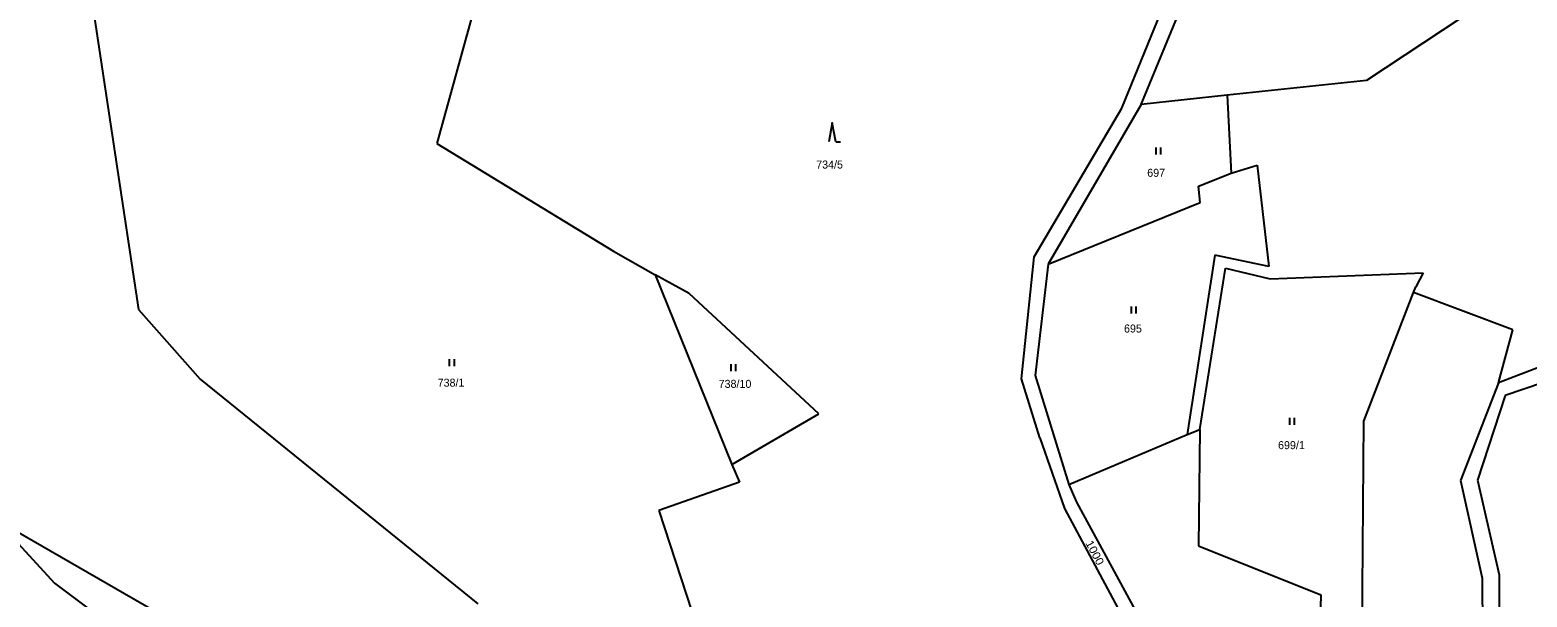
# Model space of a CAD drawing. Extents: x -744132 to -742433, y -984679 to -982287.
# Drawn here: x -743052.8 to -742734.8, y -982660.9 to -982540.5 of the extents above; entities that cross this region are included whole.
import ezdxf

# ---------------------------------------------------------------- set-up
doc = ezdxf.new("R2010")
doc.units = 0
doc.header["$LTSCALE"] = 0.68
doc.layers.add('1', color=7, linetype='Continuous', lineweight=25)
doc.layers.add('3', color=7, linetype='Continuous', lineweight=25)
doc.layers.add('2', color=7, linetype='Continuous')

msp = doc.modelspace()

# ---------------------------------------------------------------- linework, layer by layer
at = {"layer": '1'}
for p, q in [((-742956.06, -982527.23), (-742966.36, -982564.55)), ((-743040.15, -982530.76), (-743029.77, -982599.85)), ((-742820.87, -982557.06), (-742811.21, -982533.39)), ((-742816.77, -982556.28), (-742808.03, -982535.17)), ((-742744.69, -982535.17), (-742768.89, -982551.2)), ((-742768.89, -982551.2), (-742798.5, -982554.34)), ((-742798.5, -982554.34), (-742816.77, -982556.28)), ((-742798.5, -982554.34), (-742797.66, -982570.9)), ((-742839.53, -982588.68), (-742820.87, -982557.06)), ((-742816.77, -982556.28), (-742836.52, -982590.2)), ((-742966.36, -982564.55), (-742928.88, -982587.43)), ((-742797.66, -982570.9), (-742792.12, -982569.17)), ((-742792.12, -982569.17), (-742789.65, -982590.67)), ((-742804.57, -982573.63), (-742797.66, -982570.9)), ((-742804.21, -982577.12), (-742804.57, -982573.63)), ((-742836.52, -982590.2), (-742804.21, -982577.12)), ((-742928.88, -982587.43), (-742919.99, -982592.49)), ((-742842.22, -982614.55), (-742839.53, -982588.68)), ((-742801.1, -982588.28), (-742806.97, -982626.41)), ((-742789.65, -982590.67), (-742801.1, -982588.28)), ((-742912.77, -982596.45), (-742919.99, -982592.49)), ((-742919.99, -982592.49), (-742903.7, -982632.78)), ((-742836.52, -982590.2), (-742839.3, -982613.87)), ((-742804.33, -982625.3), (-742798.87, -982591.05)), ((-742798.87, -982591.05), (-742789.35, -982593.29)), ((-742789.35, -982593.29), (-742756.83, -982592.01)), ((-742756.83, -982592.01), (-742758.44, -982595.01)), ((-742758.91, -982596.23), (-742758.44, -982595.01)), ((-742885.25, -982621.97), (-742912.77, -982596.45)), ((-742769.46, -982623.53), (-742758.91, -982596.23)), ((-742737.8, -982604.17), (-742758.91, -982596.23)), ((-743029.77, -982599.85), (-743016.67, -982614.64)), ((-742740.85, -982615.41), (-742737.8, -982604.17)), ((-742703.8, -982605.92), (-742739.43, -982618.08)), ((-743016.67, -982614.64), (-742957.65, -982662.34)), ((-742838.32, -982627.08), (-742842.22, -982614.55)), ((-742839.3, -982613.87), (-742832.1, -982637)), ((-742731.79, -982611.94), (-742740.85, -982615.41)), ((-742740.85, -982615.41), (-742748.92, -982636.13)), ((-742739.43, -982618.08), (-742745.35, -982636.08)), ((-742903.7, -982632.78), (-742885.25, -982621.97)), ((-742769.83, -982672.01), (-742769.46, -982623.53)), ((-742838.32, -982627.08), (-742833.04, -982642.07)), ((-742832.1, -982637), (-742806.97, -982626.41)), ((-742806.97, -982626.41), (-742804.33, -982625.3)), ((-742804.33, -982625.3), (-742804.58, -982650.01)), ((-742903.7, -982632.78), (-742902.06, -982636.54)), ((-742902.06, -982636.54), (-742919.23, -982642.5)), ((-742832.1, -982637), (-742830.48, -982640.77)), ((-742748.92, -982636.13), (-742744.32, -982656.91)), ((-742745.35, -982636.08), (-742740.73, -982656.16)), ((-742919.23, -982642.5), (-742912.18, -982664.01)), ((-742833.04, -982642.07), (-742818.52, -982669.2)), ((-742830.48, -982640.77), (-742815.77, -982667.84)), ((-743060.05, -982644.41), (-743017.91, -982668.68)), ((-743060.05, -982644.41), (-743047.6, -982657.96)), ((-742804.58, -982650.01), (-742778.58, -982660.46)), ((-742740.73, -982656.16), (-742740.8, -982699.54)), ((-743047.6, -982657.96), (-743011.55, -982684.96)), ((-742744.32, -982656.91), (-742744.13, -982699.51)), ((-742778.58, -982660.46), (-742779.23, -982685.32))]:
    msp.add_line(p, q, dxfattribs=at)
at = {"layer": '3'}
for p, q in [((-742881.63, -982564.2), (-742880.634, -982564.2)), ((-742813.581, -982566.92), (-742813.581, -982565.42)), ((-742812.58, -982566.92), (-742812.58, -982565.42)), ((-742818.841, -982600.68), (-742818.841, -982599.18)), ((-742817.84, -982600.68), (-742817.84, -982599.18)), ((-742963.661, -982611.88), (-742963.661, -982610.38)), ((-742962.66, -982611.88), (-742962.66, -982610.38)), ((-742903.871, -982612.95), (-742903.871, -982611.45)), ((-742902.87, -982612.95), (-742902.87, -982611.45)), ((-742785.201, -982624.34), (-742785.201, -982622.84)), ((-742784.2, -982624.34), (-742784.2, -982622.84))]:
    msp.add_line(p, q, dxfattribs=at)
msp.add_lwpolyline([(-742881.63, -982564.2), (-742882.38, -982560.2), (-742883.13, -982564.2)], dxfattribs=at)

# ---------------------------------------------------------------- texts
at = {"layer": '2'}
for s, p in [('734/5', (-742885.8, -982569.895)), ('697', (-742815.48, -982571.645)), ('695', (-742820.41, -982604.725)), ('738/1', (-742966.21, -982616.225)), ('738/10', (-742906.52, -982616.475)), ('699/1', (-742787.69, -982629.495))]:
    msp.add_text(s, height=1.7, dxfattribs=at).set_placement(p)
at = {"layer": '2', "width": 1.1}
msp.add_text('1000', height=1.7, rotation=298, dxfattribs=at).set_placement((-742828.655, -982649.429))

doc.saveas('drawing.dxf')
